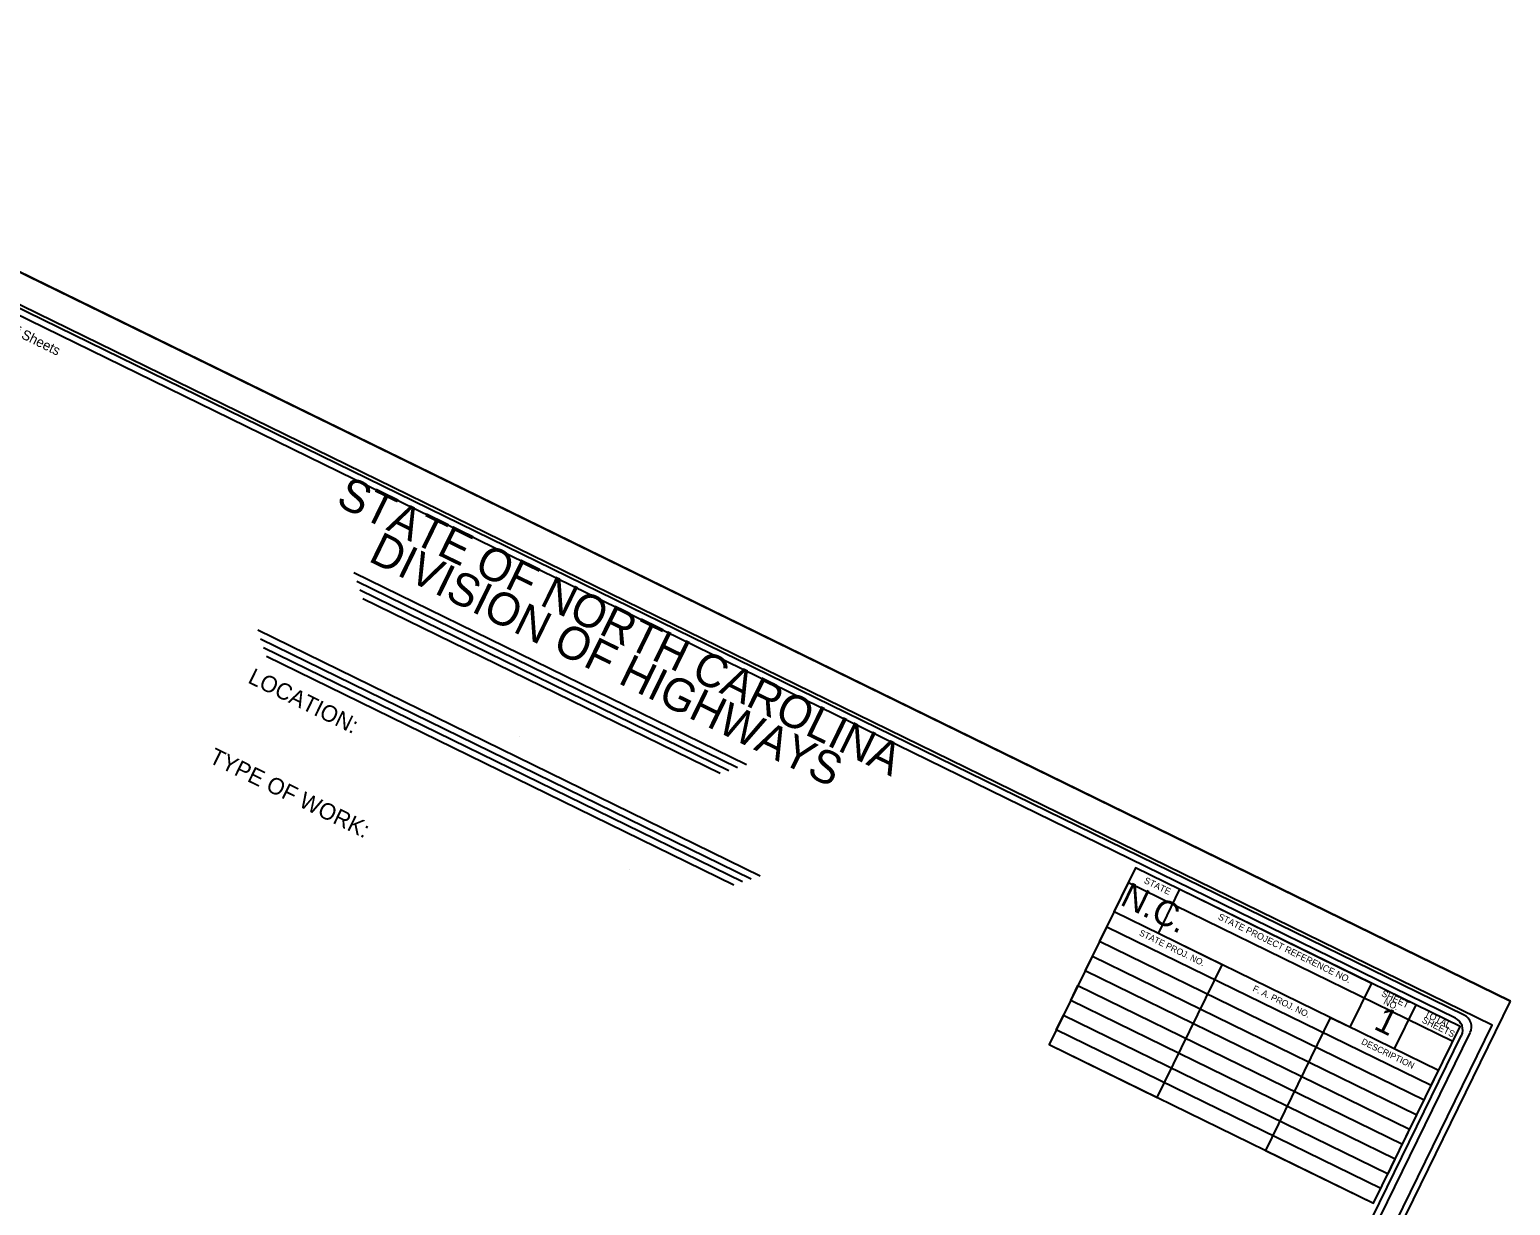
# Model space of a CAD drawing. Extents: x 1517888 to 1526099, y 633375 to 640181.
# Drawn here: x 1521570.5 to 1521683.2, y 636965.6 to 637055.2 of the extents above; entities that cross this region are included whole.
import ezdxf

# ---------------------------------------------------------------- set-up
doc = ezdxf.new("R2010")
doc.units = 0
for name, color, linetype in [('Sheet Cutting Line CELL', 7, 'Continuous'), ('Sheet Plot Border Inside CELL', 7, 'Continuous'), ('Sheet Plot Border Outside CELL', 7, 'Continuous'), ('Sheet Title CELL', 7, 'Continuous'), ('Sheet Title Data Points CELL', 7, 'Continuous')]:
    doc.layers.add(name, color=color, linetype=linetype)

msp = doc.modelspace()

# ---------------------------------------------------------------- linework, layer by layer
at = {"layer": 'Sheet Cutting Line CELL'}
msp.add_line((1521531.96, 637055.16), (1521683.24, 636981.17), dxfattribs=at)
at = {"layer": 'Sheet Plot Border Inside CELL'}
msp.add_lwpolyline([(1521485.79, 636957.79), (1521635.49, 636884.57), (1521681.85, 636979.36), (1521532.14, 637052.57)], close=True, dxfattribs=at)
at = {"layer": 'Sheet Plot Border Outside CELL'}
msp.add_lwpolyline([(1521683.24, 636981.17), (1521531.96, 637055.16), (1521483.63, 636956.35), (1521634.91, 636882.36)], close=True, dxfattribs=at)
at = {"layer": 'Sheet Title CELL'}
for p, q in [((1521595.17, 637013.83), (1521625.06, 636999.21)), ((1521595.4, 637013.16), (1521624.39, 636998.98)), ((1521595.63, 637012.49), (1521623.73, 636998.75)), ((1521595.86, 637011.83), (1521623.06, 636998.53)), ((1521587.84, 637009.45), (1521626.1, 636990.73)), ((1521588.06, 637008.78), (1521625.43, 636990.5)), ((1521588.29, 637008.11), (1521624.77, 636990.28)), ((1521588.52, 637007.44), (1521624.1, 636990.04))]:
    msp.add_line(p, q, dxfattribs=at)
for points in [[(1521679.72, 636980.11), (1521546.76, 637045.14)], [(1521679.05, 636979.89), (1521551.49, 637042.27)], [(1521648.11, 636977.87), (1521672.82, 636965.79), (1521673.37, 636966.91), (1521648.66, 636978.99), (1521649.21, 636980.12), (1521673.92, 636968.03), (1521674.47, 636969.16), (1521649.76, 636981.24), (1521650.31, 636982.36), (1521675.02, 636970.28), (1521675.56, 636971.4), (1521650.86, 636983.49), (1521651.41, 636984.61), (1521676.11, 636972.53), (1521676.66, 636973.65), (1521651.96, 636985.73), (1521652.51, 636986.85), (1521677.21, 636974.77), (1521677.76, 636975.89), (1521653.06, 636987.98), (1521654.16, 636990.22), (1521678.86, 636978.14), (1521679.41, 636979.26), (1521654.7, 636991.34), (1521648.11, 636977.87), (1521656.35, 636973.84), (1521661.29, 636983.95), (1521656.43, 636986.33), (1521658.07, 636989.7), (1521672.67, 636982.56), (1521671.02, 636979.19), (1521669.52, 636979.92), (1521664.58, 636969.82), (1521672.82, 636965.79), (1521679.41, 636979.26), (1521676.04, 636980.91), (1521674.39, 636977.54)], [(1521634.92, 636886.25), (1521680.17, 636978.78)], [(1521642.82, 636903.54), (1521679.5, 636978.55)]]:
    msp.add_lwpolyline(points, dxfattribs=at)
for centre in [(1521679.28, 636979.22), (1521678.61, 636978.99)]:
    msp.add_arc(centre, 1, 333.9377, 63.9377, dxfattribs=at)
at = {"layer": 'Sheet Title Data Points CELL'}
for p, q in [((1521607.76, 637001.36), (1521607.76, 637001.36)), ((1521616.16, 636991.21), (1521616.16, 636991.21))]:
    msp.add_line(p, q, dxfattribs=at)

# ---------------------------------------------------------------- texts
at = {"layer": 'Sheet Title CELL'}
for s, height, p in [('See Sheet 1A For Index of Sheets', 0.75, (1521558.91, 637037)), ('STATE OF NORTH CAROLINA', 2.5, (1521593.71, 637018.99)), ('DIVISION OF HIGHWAYS', 2.5, (1521596.18, 637014.73)), ('LOCATION: ', 1.25, (1521587.02, 637005.46)), ('TYPE OF WORK:', 1.25, (1521584.05, 636999.39)), ('STATE', 0.5, (1521655.29, 636990.2)), ('N.C.', 1.935, (1521653.43, 636988.56)), ('STATE PROJECT REFERENCE NO.', 0.5, (1521660.93, 636987.44)), ('STATE PROJ. NO.', 0.48, (1521654.92, 636986.22)), ('F. A. PROJ. NO.', 0.48, (1521663.57, 636981.98)), ('SHEET', 0.5, (1521673.37, 636981.6)), ('NO.', 0.5, (1521673.52, 636980.98)), ('1', 1.93, (1521672.75, 636979.11)), ('TOTAL', 0.5, (1521676.64, 636980.05)), ('SHEETS', 0.5, (1521676.45, 636979.58)), ('DESCRIPTION', 0.48, (1521671.84, 636977.94))]:
    msp.add_text(s, height=height, rotation=333.9377, dxfattribs=at).set_placement(p)

doc.saveas('drawing.dxf')
